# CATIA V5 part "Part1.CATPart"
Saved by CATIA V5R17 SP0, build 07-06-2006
Part number: Part1
Bounding box of the stored display mesh (mm): x -100 to 100, y -100 to 100, z 0 to 300
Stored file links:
  E:\Ehsan\Amoozesh\CATIA\CATIA Course\Advanced\Exercises\DMU Kinematic\5\Part1.CATPart
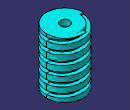
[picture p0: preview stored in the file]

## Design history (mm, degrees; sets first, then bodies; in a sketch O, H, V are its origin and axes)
Body1 (main body)
  Sketch1 on xy-plane, origin (0, 0, 0), H (1, 0, 0), V (0, 1, 0)
    circle A1 centre (0, 0) radius 100
    point P1 (0, 100)
    coincidence: A1 P1, P1 V
  Pad1: profile Sketch1, direction (0, 0, 1), length 300
  Sketch2 on zx-plane, origin (0, 0, 0), H (-1, 0, 0), V (0, 0, 1)
    point P1 (100, 300)
  Helix1: Direction Sketch2.V, RefPoint Sketch2, Pitch 50, Height 300, TaperAngle 0
  Plane1: type Normal, Curve Helix1, RefPoint Sketch2
  Sketch3 on Plane1, origin (0, -23.723, 1.8878), H (-1, 0, 0), V (0, 0.0793, 0.9968)
    line L1 (100, 310) -> (80, 310)
    line L2 (80, 310) -> (80, 290)
    line L3 (80, 290) -> (100, 290)
    line L4 (100, 290) -> (100, 310)
    horizontal: L1 H, L3 H
    vertical: L2 V, L4 V
  Slot1: profile Sketch3, centre curve Helix1
  Sketch4 on end face of Pad1, origin (0, 0, 300), H (1, 0, 0), V (0, 1, 0)
    point P1 (0, 0)
  Hole1: placed by Sketch4, at (0, 0, 300) direction (0, 0, -1), diameter 50, through (limit type 3)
